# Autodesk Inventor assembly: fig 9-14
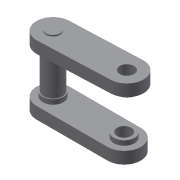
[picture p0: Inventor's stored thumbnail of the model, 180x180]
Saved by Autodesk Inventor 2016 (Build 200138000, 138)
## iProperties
Shininess: 64.0
Length Units: 11269
Angle Units: 11279
Time Units: 11290
Mass Units: 11283
Length Display Precision: 3
Angle Display Precision: 2
Created: 2002-01
Part Number: fig 9-14
Document SubType Name: Assembly
Designer: ***
Density: 0.0
Volumn: 0.0
Area: 0.0
PropertySet Name: Model Information
Control State: 0
Master: False
Checked Out: False
Author: ***
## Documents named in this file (3)
- D:\KAVITA\Autodesk Inventor_ 2016 Project_Kavita\Inventor_Part Files\Inventor_2016_Part\c09_Inv_2016\c09_inv_2016_prt\fig 9-14.iam
- D:\KAVITA\Autodesk Inventor_ 2016 Project_Kavita\Inventor_Part Files\Inventor_2016_Part\c09_Inv_2016\c09_inv_2016_prt\Part5.ipt
- D:\KAVITA\Autodesk Inventor_ 2016 Project_Kavita\Inventor_Part Files\Inventor_2016_Part\c09_Inv_2016\c09_inv_2016_prt\Part6.ipt
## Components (3 placed, 2 different names)
1. Part5:1 — Insert:1
2. Part6:1 — Insert:1, Insert:2
3. Part5:2 — Insert:2
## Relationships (2: Insert 2)
- Insert:1: Part5:1 ↔ Part6:1
- Insert:2: Part6:1 ↔ Part5:2
